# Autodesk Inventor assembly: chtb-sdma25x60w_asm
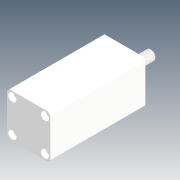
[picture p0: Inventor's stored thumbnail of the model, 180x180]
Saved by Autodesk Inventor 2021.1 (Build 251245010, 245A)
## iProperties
Company: Microsoft
Created: 2018-05
Part Number: chtb-sdma25x60w_asm
Description: STEP AP214
Document SubType Name: Assembly
Designer: user
Title: chtb-sdma25x60w_asm.STEP
Author: Windows
Revision Number: ÈÎºÎ
Sending System: SolidWorks 2015
Preprocessor: SwSTEP 2.0
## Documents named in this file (4)
- D:\Vault_2016\Projekty\Clamptek\Hydraulic\CHTB\CHTB-25\Inventor\chtb-sdma25x60w\chtb-sdma25x60w_asm.iam
- D:\Vault_2016\Projekty\Clamptek\Hydraulic\CHTB\CHTB-25\Inventor\chtb-sdma25x60w\CHTB-25QG.ipt
- D:\Vault_2016\Projekty\Clamptek\Hydraulic\CHTB\CHTB-25\Inventor\chtb-sdma25x60w\CHTB-SDMA25X60NBT.ipt
- D:\Vault_2016\Projekty\Clamptek\Hydraulic\CHTB\CHTB-25\Inventor\chtb-sdma25x60w\CHTB-SDMA25X60WHSG.ipt
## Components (3 placed, 3 different names)
1. CHTB-25QG_1
2. CHTB-SDMA25X60NBT_2
3. CHTB-SDMA25X60WHSG_3
